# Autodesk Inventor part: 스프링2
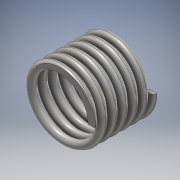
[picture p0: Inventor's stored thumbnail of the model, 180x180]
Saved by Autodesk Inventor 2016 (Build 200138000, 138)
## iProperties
Created: 2019-07
Part Number: 스프링2
Material: 강철, 탄소
Document SubType Name: Modeling
Designer: 602-01
Density: 7.85 g/cm^3
Appearance: 반연마
Mass: 7.69315 g
Surface Area: 20.0054 cm^2
Volume: 0.980019 cm^3
Author: 602-01
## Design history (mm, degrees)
sketch "스케치1"
  geometry: L1 (0, 0)-(8.5, 0); L2 (8.5, 0)-(8.5, 16); L3 (8.5, 16)-(0, 16); L4 (0, 16)-(0, 0); C1 r 1 at (8.5, 0)
  constraints: 8 end point, 2 parallel, 1 centre point, 1 coincident, 1 horizontal, 1 perpendicular
  dimensions: "d0" = 17 diameter of L2 L4; "d1" = 16 distance between parallel lines of L1 L3 (derived); "d2" = 2 diameter of C1
feature "코일1" sketch "스케치1" pitch "d3" = 10; turns "d5" = 6; dims "d4" = 16 (= d1), "d6" = 0, angle "d7" = 90 deg, angle "d8" = 90 deg, "d9" = 0, "d10" = 0
sketch "스케치2"
  geometry: L1 (-7.5, 0)-(-9.5, 0) reference; 1 further point
  constraints: 1 horizontal alignment
extrude "돌출1" cut sketch "스케치2" distance "d11" = 10; taper "d12" = 0 deg
node "작업 평면1"
sketch "스케치3"
  geometry: L1 (-1, 0)-(1, 0) reference; 1 further point
  constraints: 1 horizontal alignment
extrude "돌출2" cut sketch "스케치3" distance "d14" = 10; taper "d15" = 0 deg
node "솔리드1"
node "절단 모서리 투영1"
node "절단 모서리 투영2"
other parameters: "d13" = 90 deg
